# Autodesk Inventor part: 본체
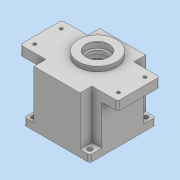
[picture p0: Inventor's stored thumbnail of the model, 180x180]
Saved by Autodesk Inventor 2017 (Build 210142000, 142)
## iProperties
Part Number: 본체
Material: 일반
Document SubType Name: Modeling
Designer: user
Density: 1 g/cm^3
Appearance: 기본값
Author: user
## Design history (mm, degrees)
sketch "스케치1"
  geometry: L1 (-70, -30)-(70, -30); L2 (70, -30)-(70, 30); L3 (70, 30)-(-70, 30); L4 (-70, 30)-(-70, -30); L5 (-70, -30)-(70, 30); L6 (70, -30)-(-70, 30); L7 (-33, -47)-(33, -47); L8 (33, -47)-(33, 47); L9 (33, 47)-(-33, 47); L10 (-33, 47)-(-33, -47); L11 (-33, -47)-(33, 47); L12 (33, -47)-(-33, 47); 1 further point
  constraints: 24 end point, 4 midpoint, 4 parallel, 2 horizontal, 2 perpendicular
  dimensions: "d0" = 140 distance of L3.end L2.end; "d1" = 60 distance of L2.end L1.end; "d2" = 66 distance of L9.end L8.end; "d3" = 94 distance of L8.end L7.end
extrude "돌출1" new body sketch "스케치1" distance "d4" = 13; taper "d5" = 0 deg
sketch "스케치2"
  geometry: L1 (33, 47)-(-33, 47); L2 (-33, 47)-(-33, -47); L3 (-33, -47)-(33, -47); L4 (33, -47)-(33, 47); L5 (33, 47)-(-33, -47); L6 (-33, 47)-(33, -47); L7 (47, 30)-(-47, 30); L8 (-47, 30)-(-47, -30); L9 (-47, -30)-(47, -30); L10 (47, -30)-(47, 30); L11 (47, 30)-(-47, -30); L12 (-47, 30)-(47, -30); 1 further point
  constraints: 24 end point, 4 midpoint, 4 parallel, 2 horizontal, 2 perpendicular
  dimensions: "d6" = 66 distance of L3.end L2.end; "d7" = 94 distance of L2.end L1.end; "d8" = 94 distance of L9.end L8.end; "d9" = 60 distance of L8.end L7.end
extrude "돌출2" join sketch "스케치2" distance "d10" = 57; taper "d11" = 0 deg
sketch "스케치3"
  geometry: L1 (47, 47)-(-47, 47); L2 (-47, 47)-(-47, -47); L3 (-47, -47)-(47, -47); L4 (47, -47)-(47, 47); L5 (47, 47)-(-47, -47); L6 (-47, 47)-(47, -47); 1 further point
  constraints: 12 end point, 2 midpoint, 2 parallel, 1 horizontal, 1 perpendicular
  dimensions: "d12" = 94 distance of L3.end L2.end; "d13" = 94 distance of L2.end L1.end
extrude "돌출3" join sketch "스케치3" distance "d14" = 10; taper "d15" = 0 deg
sketch "스케치4"
  geometry: C1 r 27.5 at (0, 11); 1 further point
  constraints: 1 centre point, 1 vertical alignment
  dimensions: "d16" = 55 diameter of C1; "d17" = 11 distance of point (0, 0) C1.centre
extrude "돌출4" join sketch "스케치4" distance "d18" = 7; taper "d19" = 0 deg
sketch "스케치5"
  geometry: C1 r 16 at (0, 0); 1 further point
  constraints: 1 centre point
  dimensions: "d20" = 32 diameter of C1
extrude "돌출5" cut sketch "스케치5" distance "d21" = 8.3; taper "d22" = 0 deg
sketch "스케치6"
  geometry: C1 r 16 at (0, 0) reference; C2 r 12.5 at (0, 0); 1 further point
  constraints: 1 centre point, 1 coincident
  dimensions: "d23" = 25 diameter of C2
extrude "돌출6" cut sketch "스케치6" distance "d24" = 4.7; taper "d25" = 0 deg
sketch "스케치7"
  geometry: C1 r 43 at (0, 0); 1 further point
  constraints: 1 centre point, 1 coincident
  dimensions: "d26" = 86 diameter of C1
extrude "돌출7" cut sketch "스케치7" distance "d27" = 9; taper "d28" = 0 deg
sketch "스케치8"
  geometry: L1 (35.778, 3.994)-(39.8, 3.994); L2 (35.778, -3.994)-(39.8, -3.994); L3 (-35.778, 3.994)-(-39.8, 3.994); L4 (-35.778, -3.994)-(-39.8, -3.994); A1 r 40 centre (0, 0) between (39.8, 3.994) and (39.8, -3.994); A2 r 36 centre (0, 0) between (36, 0) and (-36, 0); A3 r 4 centre (36, 0) between (36.222, 3.994) and (36.222, -3.994); A4 r 4 centre (-36, 0) between (-36.222, -3.994) and (-36.222, 3.994); 1 further point
  constraints: 18 point on circle, 8 end point, 4 centre point, 4 point on line, 3 horizontal, 2 coincident, 2 horizontal alignment, 1 parallel
  dimensions: "d29" = 80 diameter of A1; "d30" = 72 diameter of A2; "d31" = 8 diameter of A3; "d32" = 8 diameter of A4
extrude "돌출8" cut sketch "스케치8" distance "d33" = 62; taper "d34" = 0 deg
sketch "스케치9"
  geometry: C1 r 21 at (0, 11); C2 r 15 at (0, -20); 1 further point
  constraints: 2 centre point, 2 vertical alignment
  dimensions: "d35" = 42 diameter of C1; "d36" = 30 diameter of C2; "d37" = 11 distance of point (0, 0) C1.centre; "d38" = 20 distance of C2.centre point (0, 0)
extrude "돌출9" join sketch "스케치9" distance "d39" = 7; taper "d40" = 0 deg
sketch "스케치10"
  geometry: C1 r 17.5 at (0, 11); A1 r 21 centre (0, 11) between (8.978, -7.984) and (-8.978, -7.984) reference; A2 r 15 centre (0, -20) between (-8.978, -7.984) and (8.978, -7.984) reference; 1 further point
  constraints: 1 centre point, 1 coincident
  dimensions: "d41" = 35 diameter of C1
extrude "돌출10" cut sketch "스케치10" distance "d43" = 10; taper "d44" = 0 deg
sketch "스케치11"
  geometry: C1 r 11 at (0, -20); A1 r 15 centre (0, -20) between (-8.978, -7.984) and (8.978, -7.984) reference; 1 further point
  constraints: 1 centre point, 1 coincident
  dimensions: "d45" = 22 diameter of C1
extrude "돌출11" cut sketch "스케치11" distance "d46" = 7; taper "d47" = 0 deg
sketch "스케치12"
  geometry: C1 r 9.5 at (0, 0); 1 further point
  constraints: 1 centre point
  dimensions: "d48" = 19 diameter of C1
extrude "돌출12" cut sketch "스케치12" distance "d49" = 3; taper "d50" = 0 deg
sketch "스케치13"
  geometry: 2 further points
  dimensions: "d51" = 60 horizontal distance of point (0, 0) point (60, -19); "d52" = 19 vertical distance of point (0, 0) point (60, -19)
hole "구멍1" sketch "스케치13" at (60, -19) diameter "d53" = 4.5; stored, may be unused: countersink angle "d57" = 90 deg, drill point angle "d59" = 118 deg; dims "d54" = 6, "d55" = 10, "d56" = 5, "d58" = 8
sketch "스케치14"
  geometry: 2 further points
  dimensions: "d66" = 40 horizontal distance of point (0, 0) point (40, -40); "d67" = 40 horizontal distance of point (0, 0) point (40, -40)
hole "구멍2" sketch "스케치14" at (40, -40) diameter "d68" = 7; stored, may be unused: countersink angle "d72" = 90 deg, drill point angle "d74" = 118 deg; dims "d69" = 6, "d70" = 10, "d71" = 5, "d73" = 8
sketch "스케치15"
  geometry: A1 r 4 centre (36, 0) between (36.222, 3.994) and (36.222, -3.994) reference; A2 r 4 centre (-36, 0) between (-36.222, -3.994) and (-36.222, 3.994) reference; 3 further points
  constraints: 2 coincident
hole "구멍3" sketch "스케치15" at (36, 0), (-36, 0) diameter "d81" = 3.242; stored, may be unused: countersink angle "d85" = 90 deg, drill point angle "d87" = 118 deg; dims "d82" = 7, "d83" = 10, "d84" = 5, "d86" = 9
chamfer "모따기1" distance "d88" = 0.8; stored, may be unused: second distance "d89" = 2, angle "d90" = 30 deg
fillet "모깎기1" dims "d91" = 3
fillet "모깎기2" dims "d92" = 3
fillet "모깎기3" dims "d93" = 3
chamfer "모따기2" distance "d94" = 1; stored, may be unused: second distance "d95" = 2, angle "d96" = 45 deg
chamfer "모따기3" distance "d97" = 1; stored, may be unused: second distance "d98" = 2, angle "d99" = 45 deg
chamfer "모따기4" distance "d100" = 1; stored, may be unused: second distance "d101" = 2, angle "d102" = 45 deg
sketch "스케치16"
  geometry: L1 (-11, 80)-(77, 80) reference; L2 (0, 70)-(0, 0) reference; 2 further points
  constraints: 1 other
  dimensions: "d103" = 40 distance from line of L1 point (33, 40); "d104" = 33 distance from line of point (33, 40) L2
feature "엠보싱1" sketch "스케치16" dims "d0" = 140, "d1" = 60, "d8" = 94, "d9" = 60, "d105" = 0.5, "d106" = 0
node "솔리드1"
pattern_linear "직사각형 패턴1" dims "d62" = 38, "d65" = 120
pattern_linear "직사각형 패턴2" dims "d77" = 80, "d80" = 80
